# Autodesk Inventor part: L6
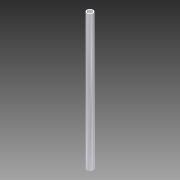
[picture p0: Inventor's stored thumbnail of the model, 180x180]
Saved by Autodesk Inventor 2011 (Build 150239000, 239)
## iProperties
Created: 2014-02
Part Number: L6
Document SubType Name: Modeling
Designer: Evgeny
Density: 1 g/cm^3
Author: Evgeny
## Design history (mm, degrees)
sketch "Эскиз1"
  geometry: C1 r 4 at (0, 0); 1 further point
  constraints: 1 centre point, 1 coincident
  dimensions: "d0" = 8 diameter of C1
extrude "Выдавливание1" new body sketch "Эскиз1" distance "d1" = 172; taper "d2" = 0 deg
feature "Оболочка1" dims "d3" = 1
node "Твердое тело1"
